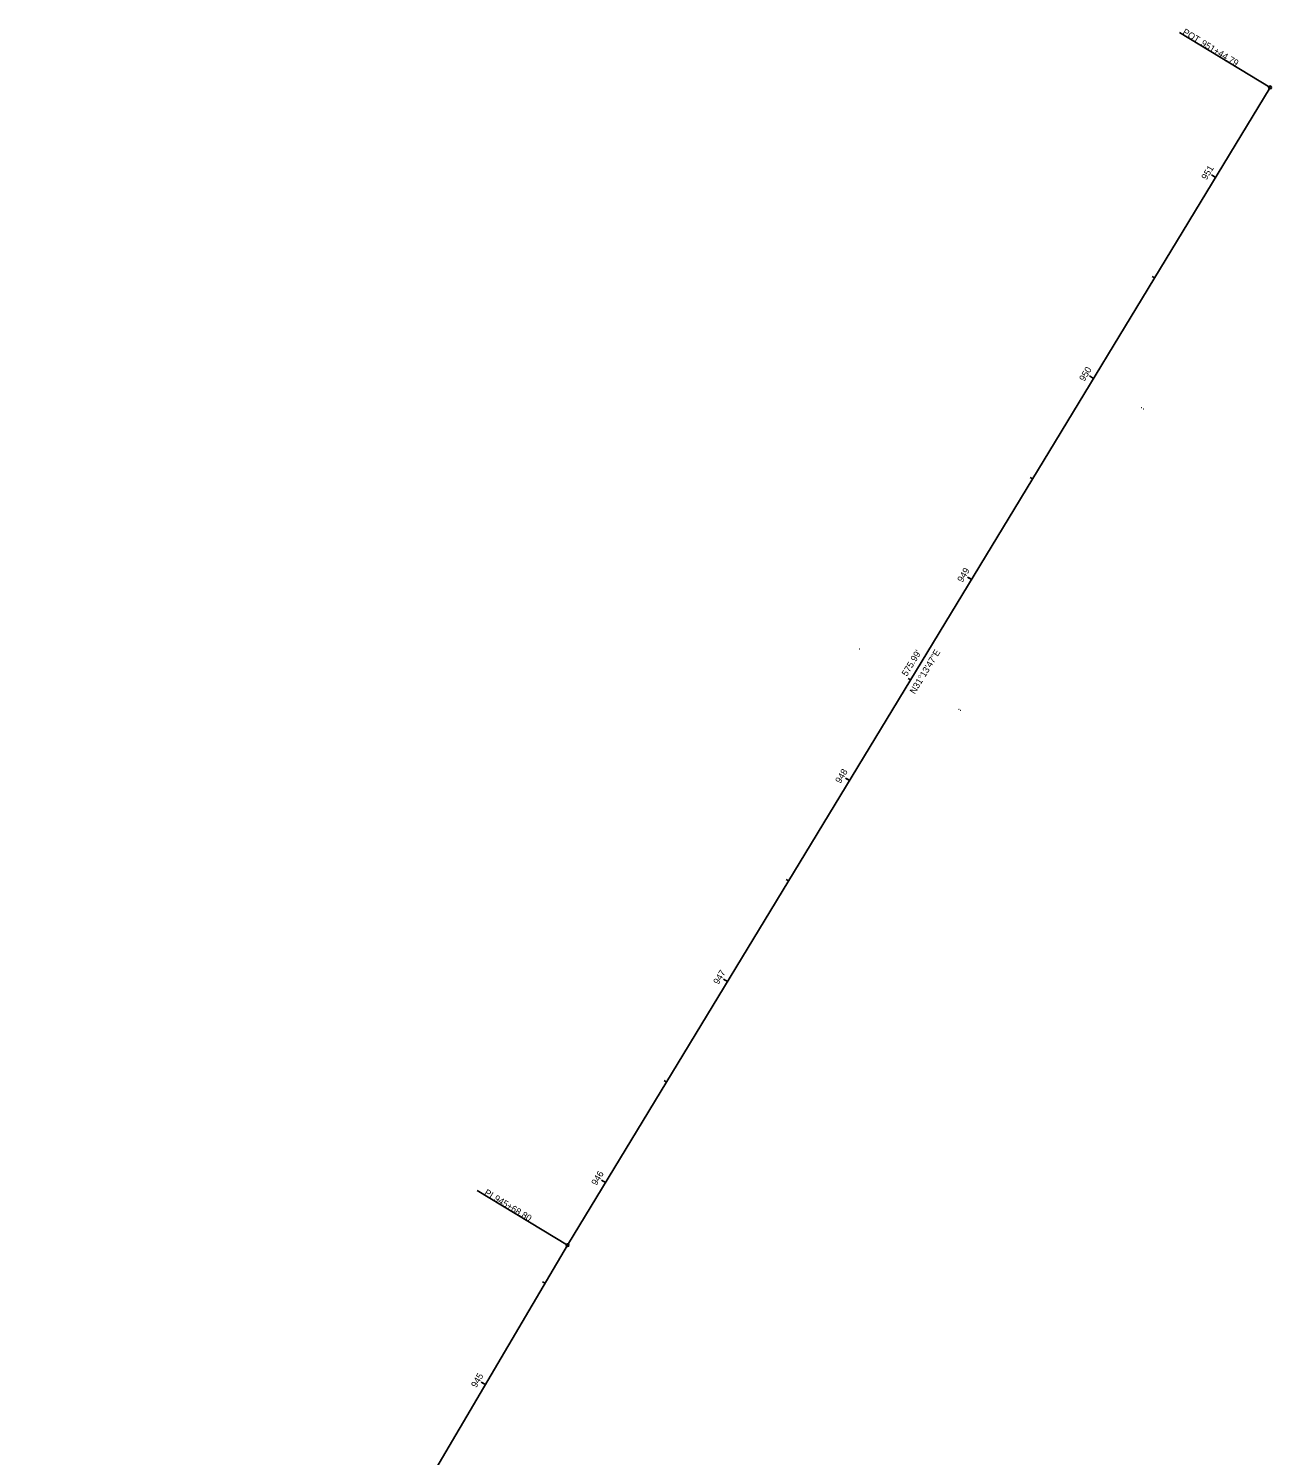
# Model space of a CAD drawing. Extents: x 1978725 to 1979446, y 230316 to 232755.
# Drawn here: x 1978917 to 1979446, y 232148 to 232755 of the extents above; entities that cross this region are included whole.
import ezdxf

# ---------------------------------------------------------------- set-up
doc = ezdxf.new("R2010")
doc.units = 0
for name, color, linetype in [('_CIVIL_CONSTRUCTION', 7, 'Continuous'), ('GE_X_Alignment', 7, 'Continuous'), ('GE_X_Alignment_1000_Stations', 7, 'Continuous'), ('GE_X_Alignment_100_Stations', 7, 'Continuous'), ('GE_X_Alignment_500_Stations', 7, 'Continuous')]:
    doc.layers.add(name, color=color, linetype=linetype)

msp = doc.modelspace()

# ---------------------------------------------------------------- linework, layer by layer
at = {"layer": '_CIVIL_CONSTRUCTION'}
for centre in [(1979390.38, 232593.55), (1979391.22, 232593.02), (1979270.41, 232490.84), (1979312.75, 232465.29), (1979313.45, 232464.76)]:
    msp.add_circle(centre, 0.0000833, dxfattribs=at)
at = {"layer": 'GE_X_Alignment'}
for p, q in [((1979146.28, 232237.28), (1979444.91, 232729.8)), ((1978917.16, 231848.52), (1979146.28, 232237.28))]:
    msp.add_line(p, q, dxfattribs=at)
at = {"layer": 'GE_X_Alignment_1000_Stations'}
for p, q in [((1979444.91, 232729.8), (1979406.44, 232753.13)), ((1979369.85, 232605.99), (1979368.14, 232607.03)), ((1979146.28, 232237.28), (1979107.8, 232260.61)), ((1979111.35, 232178), (1979110.32, 232178.61))]:
    msp.add_line(p, q, dxfattribs=at)
for centre in [(1979444.91, 232729.8), (1979146.28, 232237.28)]:
    msp.add_circle(centre, 0.6, dxfattribs=at)
at = {"layer": 'GE_X_Alignment_100_Stations'}
for p, q in [((1979444.91, 232729.8), (1979406.44, 232753.13)), ((1979421.69, 232691.5), (1979419.98, 232692.54)), ((1979395.77, 232648.75), (1979394.74, 232649.37)), ((1979369.85, 232605.99), (1979368.14, 232607.03)), ((1979343.92, 232563.24), (1979342.9, 232563.86)), ((1979318, 232520.48), (1979316.29, 232521.52)), ((1979292.08, 232477.73), (1979291.05, 232478.35)), ((1979266.15, 232434.97), (1979264.44, 232436.01)), ((1979240.23, 232392.22), (1979239.2, 232392.84)), ((1979214.31, 232349.46), (1979212.6, 232350.5)), ((1979188.38, 232306.71), (1979187.36, 232307.33)), ((1979162.46, 232263.96), (1979160.75, 232264.99)), ((1979146.28, 232237.28), (1979107.8, 232260.61)), ((1979136.74, 232221.08), (1979135.7, 232221.69)), ((1979111.35, 232178), (1979109.63, 232179.02))]:
    msp.add_line(p, q, dxfattribs=at)
for centre in [(1979444.91, 232729.8), (1979146.28, 232237.28)]:
    msp.add_circle(centre, 0.6, dxfattribs=at)
at = {"layer": 'GE_X_Alignment_500_Stations'}
for p, q in [((1979444.91, 232729.8), (1979406.44, 232753.13)), ((1979421.69, 232691.5), (1979420.67, 232692.13)), ((1979369.85, 232605.99), (1979368.14, 232607.03)), ((1979318, 232520.48), (1979316.97, 232521.11)), ((1979266.15, 232434.97), (1979265.13, 232435.6)), ((1979214.31, 232349.46), (1979213.28, 232350.09)), ((1979162.46, 232263.96), (1979161.43, 232264.58)), ((1979146.28, 232237.28), (1979107.8, 232260.61)), ((1979111.35, 232178), (1979109.63, 232179.02))]:
    msp.add_line(p, q, dxfattribs=at)
for centre in [(1979444.91, 232729.8), (1979146.28, 232237.28)]:
    msp.add_circle(centre, 0.6, dxfattribs=at)

# ---------------------------------------------------------------- texts
at = {"layer": 'GE_X_Alignment_1000_Stations'}
for s, rotation, p in [('POT', 328.77025, (1979407.44, 232752.58)), ('951+44.79', 328.77025, (1979415.25, 232747.84)), ('950', 58.77025, (1979365.97, 232604.51)), ("575.99'", 58.77025, (1979290.52, 232479.03)), ('N31°13\'47"E', 58.77025, (1979293.91, 232471.49)), ('PI', 328.77025, (1979110.64, 232258.94)), ('945+68.80', 328.77025, (1979114.73, 232256.46))]:
    msp.add_text(s, height=2.8, rotation=rotation, dxfattribs=at).set_placement(p)
at = {"layer": 'GE_X_Alignment_100_Stations'}
for s, rotation, p in [('POT', 328.77025, (1979407.44, 232752.58)), ('951+44.79', 328.77025, (1979415.25, 232747.84)), ('951', 58.77025, (1979417.9, 232690.16)), ('950', 58.77025, (1979365.97, 232604.51)), ('949', 58.77025, (1979314.14, 232519.02)), ("575.99'", 58.77025, (1979290.52, 232479.03)), ('N31°13\'47"E', 58.77025, (1979293.91, 232471.49)), ('948', 58.77025, (1979262.27, 232433.49)), ('947', 58.77025, (1979210.4, 232347.93)), ('946', 58.77025, (1979158.58, 232262.47)), ('PI', 328.77025, (1979110.64, 232258.94)), ('945+68.80', 328.77025, (1979114.73, 232256.46)), ('945', 59.48656, (1979107.48, 232176.46))]:
    msp.add_text(s, height=2.8, rotation=rotation, dxfattribs=at).set_placement(p)
at = {"layer": 'GE_X_Alignment_500_Stations'}
for s, rotation, p in [('POT', 328.77025, (1979407.44, 232752.58)), ('951+44.79', 328.77025, (1979415.25, 232747.84)), ('950', 58.77025, (1979365.97, 232604.51)), ("575.99'", 58.77025, (1979290.52, 232479.03)), ('N31°13\'47"E', 58.77025, (1979293.91, 232471.49)), ('PI', 328.77025, (1979110.64, 232258.94)), ('945+68.80', 328.77025, (1979114.73, 232256.46)), ('945', 59.48656, (1979107.48, 232176.46))]:
    msp.add_text(s, height=2.8, rotation=rotation, dxfattribs=at).set_placement(p)

doc.saveas('drawing.dxf')
